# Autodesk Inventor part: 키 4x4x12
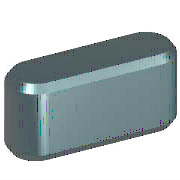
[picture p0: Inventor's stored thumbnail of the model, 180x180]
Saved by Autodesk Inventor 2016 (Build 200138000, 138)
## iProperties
IsCustomPart: 1
Created: 2012-02
Part Number: 키 4x4x12
Material: 강철, 연강
Description: 키 및 해당 키홈
Document SubType Name: Modeling
Standard: KS B 1311
Designer: mduedu
Standards Organization: KS
Language: ko-KR
Size Designation: 4 x 4 x 12
Categories: <MemberInstance><Categories><Category DisplayName="샤프트 부품" InternalName="7f7aeb1f-a693-4053-b835-cee3144e0d98" Mnemonic="SHFT"><Category DisplayName="키" Interna
Density: 1 g/cm^3
Appearance: 노란색
Author: mduedu
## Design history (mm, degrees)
workplane "Work Plane1"
workplane "Work Plane2"
sketch "스케치1"
  geometry: L1 (2, 2)-(10, 2); L2 (10, -2)-(2, -2); L3 (0, 9.4)-(0, -7.4) reference; L4 (-5, 0)-(30, 0) reference; L5 (12, 0)-(12, 7); A1 r 2 centre (2, 0) between (2, 2) and (2, -2); A2 r 2 centre (10, 0) between (10, -2) and (10, 2)
  constraints: 6 end point, 5 point on circle, 4 tangent, 3 point on line, 2 centre point, 1 horizontal, 1 parallel, 1 perpendicular
  dimensions: "d0" = 2 radius of A1 (= 0.5 x PB); "d13" = 2 radius of A2 (= 0.5 x PB); "d14" = 12 distance between parallel lines of L5 L3 (= NLG)
extrude "본체1" new body sketch "스케치1" taper "d3" = 0 deg; stored distance "d4" = 10
workplane "Work Plane3"
body "Solid1"
chamfer "모따기1" distance "d8" = 0.25 (= PHH); stored, may be unused: second distance "d9" = 0.25 (= PHH), angle "d15" = 45 deg
other parameters: "d1" = -2.5 (= -PNT), "d2" = 1.5 (= PH - PNT), "NLG" = 12 [user parameter; used in 3 equation terms], "PB" = 4 [user parameter; used in 2 equation terms], "PNT" = 2.5 [user parameter; used in 2 equation terms], "PH" = 4 [user parameter; used in 1 equation term], "PHH" = 0.25 [user parameter; used in 2 equation terms], "d10" = 0, "d16" = 0, "d17" = 0, "d18" = 0, "PLB2" = 12 (= NLG) [user parameter], "WDMAX" = 12 [user parameter], "PLB1" = 12 (= NLG) [user parameter], "RR" = 0.08 [user parameter], "PUEB" = 1.8 [user parameter]
